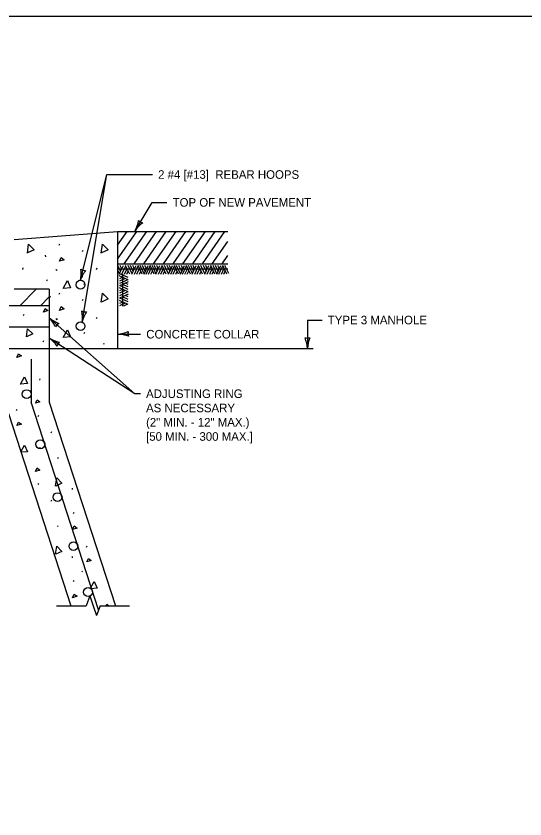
# Model space of a CAD drawing. Extents: x 49991.4 to 50021, y 49987.6 to 50011.4.
# Drawn here: x 50005.05 to 50008.62, y 49993.37 to 49999 of the extents above; entities that cross this region are included whole.
import ezdxf

# ---------------------------------------------------------------- set-up
doc = ezdxf.new("R2010")
doc.units = 0
for name, color, linetype in [('Level 1', 7, 'Continuous'), ('Level 2', 7, 'Continuous'), ('Level 3', 7, 'Continuous'), ('Level 4', 7, 'Continuous'), ('Level 6', 7, 'Continuous')]:
    doc.layers.add(name, color=color, linetype=linetype)

msp = doc.modelspace()

# ---------------------------------------------------------------- linework, layer by layer
at = {"layer": 'Level 1'}
for p, q in [((50005.0384, 49997.4313), (50005.7649, 49997.4869)), ((50005.7649, 49997.2938), (50005.9001, 49997.4869)), ((50005.7649, 49997.4869), (50006.5384, 49997.4869)), ((50005.7649, 49997.4869), (50005.7649, 49996.6669)), ((50005.7651, 49997.3923), (50005.8314, 49997.4869)), ((50005.8113, 49997.2619), (50005.9688, 49997.4869)), ((50005.8799, 49997.2619), (50006.0374, 49997.4869)), ((50005.9486, 49997.2619), (50006.1062, 49997.4869)), ((50006.0173, 49997.2619), (50006.1748, 49997.4869)), ((50006.0859, 49997.2619), (50006.2435, 49997.4869)), ((50006.1546, 49997.2619), (50006.3121, 49997.4869)), ((50006.2232, 49997.2619), (50006.3808, 49997.4869)), ((50006.2919, 49997.2619), (50006.4495, 49997.4869)), ((50006.3606, 49997.2619), (50006.5181, 49997.4869)), ((50005.3541, 49997.3925), (50005.3585, 49997.4022)), ((50006.4292, 49997.2619), (50006.5384, 49997.4178)), ((50005.2575, 49997.3209), (50005.2586, 49997.3112)), ((50005.5187, 49997.3481), (50005.523, 49997.3579)), ((50006.498, 49997.2619), (50006.5384, 49997.3197)), ((50005.7649, 49997.2619), (50006.5384, 49997.2619)), ((50005.0986, 49997.2225), (50005.1029, 49997.2323)), ((50005.3314, 49997.2225), (50005.3357, 49997.216)), ((50005.3357, 49997.2201), (50005.3401, 49997.2136)), ((50005.6172, 49997.2225), (50005.6216, 49997.2323)), ((50005.7649, 49997.2254), (50006.5384, 49997.2254)), ((50005.7784, 49997.1924), (50005.7649, 49997.2213)), ((50005.786, 49997.2088), (50005.7668, 49997.2499)), ((50005.7767, 49997.1886), (50005.8051, 49997.2499)), ((50005.7942, 49997.2265), (50005.7836, 49997.2499)), ((50005.795, 49997.1886), (50005.8222, 49997.2471)), ((50005.8125, 49997.1886), (50005.831, 49997.2284)), ((50005.8495, 49997.1886), (50005.8209, 49997.2499)), ((50005.8299, 49997.1886), (50005.8396, 49997.2097)), ((50005.8662, 49997.1903), (50005.8386, 49997.2499)), ((50005.875, 49997.2093), (50005.8563, 49997.2499)), ((50005.8655, 49997.1886), (50005.8939, 49997.2499)), ((50005.883, 49997.2272), (50005.8727, 49997.2499)), ((50005.8824, 49997.1886), (50005.9095, 49997.2469)), ((50005.9, 49997.1886), (50005.9183, 49997.2284)), ((50005.9369, 49997.1886), (50005.9082, 49997.2499)), ((50005.9179, 49997.1886), (50005.9272, 49997.2091)), ((50005.9508, 49997.1905), (50005.9232, 49997.2499)), ((50005.959, 49997.2082), (50005.9398, 49997.2499)), ((50005.9499, 49997.1886), (50005.9783, 49997.2501)), ((50005.9676, 49997.2267), (50005.9569, 49997.2499)), ((50005.9651, 49997.1886), (50005.9925, 49997.248)), ((50005.9819, 49997.1886), (50006.0009, 49997.2303)), ((50006.0204, 49997.1886), (50005.992, 49997.2499)), ((50005.9981, 49997.1886), (50006.0091, 49997.2128)), ((50006.0204, 49997.2213), (50006.0072, 49997.2499)), ((50006.0339, 49997.1924), (50006.0204, 49997.2213)), ((50006.0415, 49997.2088), (50006.0223, 49997.2499)), ((50006.0322, 49997.1886), (50006.0606, 49997.2499)), ((50006.0497, 49997.2265), (50006.039, 49997.2499)), ((50006.0505, 49997.1886), (50006.0777, 49997.2471)), ((50006.068, 49997.1886), (50006.0865, 49997.2284)), ((50006.1049, 49997.1886), (50006.0764, 49997.2499)), ((50006.0853, 49997.1886), (50006.095, 49997.2097)), ((50006.1217, 49997.1903), (50006.0941, 49997.2499)), ((50006.1305, 49997.2093), (50006.1118, 49997.2499)), ((50006.1209, 49997.1886), (50006.1493, 49997.2499)), ((50006.1385, 49997.2272), (50006.1282, 49997.2499)), ((50006.1379, 49997.1886), (50006.165, 49997.2469)), ((50006.1554, 49997.1886), (50006.1737, 49997.2284)), ((50006.1924, 49997.1886), (50006.1636, 49997.2499)), ((50006.1733, 49997.1886), (50006.1827, 49997.2091)), ((50006.2063, 49997.1905), (50006.1787, 49997.2499)), ((50006.2145, 49997.2082), (50006.1952, 49997.2499)), ((50006.2053, 49997.1886), (50006.2337, 49997.2501)), ((50006.2231, 49997.2267), (50006.2124, 49997.2499)), ((50006.2206, 49997.1886), (50006.248, 49997.248)), ((50006.2373, 49997.1886), (50006.2564, 49997.2303)), ((50006.2758, 49997.1886), (50006.2474, 49997.2499)), ((50006.2535, 49997.1886), (50006.2646, 49997.2128)), ((50006.2758, 49997.2213), (50006.2627, 49997.2499)), ((50006.2893, 49997.1924), (50006.2758, 49997.2213)), ((50006.297, 49997.2088), (50006.2777, 49997.2499)), ((50006.2876, 49997.1886), (50006.316, 49997.2499)), ((50006.3052, 49997.2265), (50006.2945, 49997.2499)), ((50006.3059, 49997.1886), (50006.3332, 49997.2471)), ((50006.3234, 49997.1886), (50006.3419, 49997.2284)), ((50006.3604, 49997.1886), (50006.3318, 49997.2499)), ((50006.3408, 49997.1886), (50006.3505, 49997.2097)), ((50006.3772, 49997.1903), (50006.3495, 49997.2499)), ((50006.3859, 49997.2093), (50006.3673, 49997.2499)), ((50006.3764, 49997.1886), (50006.4048, 49997.2499)), ((50006.3939, 49997.2272), (50006.3836, 49997.2499)), ((50006.3934, 49997.1886), (50006.4204, 49997.2469)), ((50006.4109, 49997.1886), (50006.4292, 49997.2284)), ((50006.4478, 49997.1886), (50006.4191, 49997.2499)), ((50006.4288, 49997.1886), (50006.4381, 49997.2091)), ((50006.4617, 49997.1905), (50006.4341, 49997.2499)), ((50006.4699, 49997.2082), (50006.4507, 49997.2499)), ((50006.4608, 49997.1886), (50006.4892, 49997.2501)), ((50006.4785, 49997.2267), (50006.4678, 49997.2499)), ((50006.476, 49997.1886), (50006.5035, 49997.248)), ((50006.4928, 49997.1886), (50006.5118, 49997.2303)), ((50006.5313, 49997.1886), (50006.5029, 49997.2499)), ((50006.509, 49997.1886), (50006.52, 49997.2128)), ((50006.5313, 49997.2213), (50006.5181, 49997.2499)), ((50006.5448, 49997.1924), (50006.5313, 49997.2213)), ((50005.2675, 49997.1423), (50005.2718, 49997.152)), ((50005.8382, 49997.149), (50005.7767, 49997.1774)), ((50005.8001, 49997.1668), (50005.7769, 49997.1561)), ((50005.8186, 49997.1582), (50005.7769, 49997.139)), ((50005.8363, 49997.15), (50005.7769, 49997.1224)), ((50005.8382, 49997.1643), (50005.7788, 49997.1917)), ((50005.8014, 49996.9641), (50005.8014, 49997.1891)), ((50005.5295, 49997.1174), (50005.5339, 49997.1271)), ((50005.8382, 49997.1361), (50005.7769, 49997.1073)), ((50005.8382, 49997.0647), (50005.7769, 49997.093)), ((50005.8382, 49997.0816), (50005.7799, 49997.1087)), ((50005.8382, 49997.0991), (50005.7984, 49997.1174)), ((50005.8382, 49997.117), (50005.8177, 49997.1264)), ((50005.285, 49997.0845), (50005.0384, 49997.0845)), ((50005.1926, 49997.0845), (50005.0792, 49996.9669)), ((50005.285, 49997.0845), (50005.285, 49996.2919)), ((50005.3541, 49997.0483), (50005.3585, 49997.0581)), ((50005.6649, 49997.0481), (50005.6692, 49997.0416)), ((50005.7996, 49997.0822), (50005.7769, 49997.0719)), ((50005.8175, 49997.0742), (50005.7769, 49997.0555)), ((50005.8365, 49997.0654), (50005.7769, 49997.0378)), ((50005.8382, 49997.0487), (50005.7769, 49997.0201)), ((50005.8382, 49997.029), (50005.8171, 49997.0387)), ((50005.285, 49997.0302), (50005.2238, 49996.9669)), ((50005.5187, 49997.0039), (50005.523, 49997.0137)), ((50005.8382, 49996.9759), (50005.7769, 49997.0043)), ((50005.8003, 49996.9934), (50005.7769, 49996.9827)), ((50005.818, 49996.9852), (50005.7769, 49996.966)), ((50005.8382, 49996.9942), (50005.7797, 49997.0214)), ((50005.8382, 49997.0117), (50005.7984, 49997.0302)), ((50005.8344, 49996.9776), (50005.8055, 49996.9641)), ((50005.285, 49996.9669), (50004.9724, 49996.9669)), ((50005.1048, 49996.8988), (50005.1087, 49996.9078)), ((50005.3314, 49996.8783), (50005.3357, 49996.8718)), ((50005.3357, 49996.8759), (50005.3401, 49996.8694)), ((50005.6172, 49996.8783), (50005.6216, 49996.8881)), ((50005.285, 49996.8169), (50003.1598, 49996.8169)), ((50005.5295, 49996.7732), (50005.5339, 49996.7829)), ((50005.2425, 49996.714), (50005.2467, 49996.723)), ((50005.6649, 49996.7039), (50005.6692, 49996.6974)), ((50002.6613, 49996.6669), (50005.7649, 49996.6669)), ((50005.1578, 49996.5919), (50005.1578, 49996.2919)), ((50005.2181, 49996.4446), (50005.222, 49996.4536)), ((50004.9724, 49996.2919), (50005.4368, 49994.863)), ((50005.6315, 49994.8343), (50005.1578, 49996.2919)), ((50005.285, 49996.2919), (50005.7491, 49994.863)), ((50005.0564, 49996.2316), (50005.0603, 49996.2406)), ((50005.2082, 49996.1908), (50005.2121, 49996.1998)), ((50005.2991, 49996.075), (50005.303, 49996.084)), ((50005.2181, 49995.9661), (50005.222, 49995.9751)), ((50005.3429, 49995.9022), (50005.3471, 49995.8962)), ((50005.2082, 49995.7123), (50005.2121, 49995.7213)), ((50005.4458, 49995.6874), (50005.4467, 49995.6784)), ((50005.2991, 49995.5965), (50005.303, 49995.6055)), ((50005.5139, 49995.5848), (50005.5154, 49995.5827)), ((50005.4548, 49995.5107), (50005.459, 49995.5197)), ((50005.3429, 49995.4237), (50005.3471, 49995.4177)), ((50005.546, 49995.2749), (50005.5502, 49995.2839)), ((50005.4458, 49995.2089), (50005.4467, 49995.1999)), ((50005.5139, 49995.1063), (50005.5178, 49995.1003)), ((50005.4548, 49995.0322), (50005.459, 49995.0412))]:
    msp.add_line(p, q, dxfattribs=at)
msp.add_lwpolyline([(49999.3835, 49998.9992), (50016.7501, 49998.9992), (50016.7501, 49987.7988), (49999.3835, 49987.7988)], close=True, dxfattribs=at)
for points in [[(50005.1318, 49997.3369), (50005.1404, 49997.3988), (50005.1792, 49997.3587), (50005.1328, 49997.3373)], [(50005.6504, 49997.3369), (50005.659, 49997.3988), (50005.6978, 49997.3587), (50005.6514, 49997.3373)], [(50005.3563, 49997.2788), (50005.3693, 49997.3059), (50005.3909, 49997.2896), (50005.3563, 49997.2788)], [(50005.3834, 49997.0881), (50005.4126, 49997.1433), (50005.4353, 49997.0925), (50005.3845, 49997.0881)], [(50005.285, 49997.0379), (50005.2946, 49997.0308), (50005.285, 49997.0278)], [(50005.6504, 49996.9927), (50005.659, 49997.0546), (50005.6978, 49997.0146), (50005.6514, 49996.9931)], [(50005.2438, 49996.923), (50005.2558, 49996.9479), (50005.2759, 49996.9329), (50005.2438, 49996.923)], [(50005.3563, 49996.9346), (50005.3693, 49996.9617), (50005.3909, 49996.9455), (50005.3563, 49996.9346)], [(50005.1256, 49996.749), (50005.1334, 49996.806), (50005.1691, 49996.7691), (50005.1265, 49996.749)], [(50005.3834, 49996.744), (50005.4126, 49996.7992), (50005.4353, 49996.7483), (50005.3845, 49996.744)], [(50005.0582, 49996.6051), (50005.0702, 49996.63), (50005.0903, 49996.615), (50005.0582, 49996.6051)], [(50005.0834, 49996.4176), (50005.1104, 49996.4686), (50005.1314, 49996.4215), (50005.0843, 49996.4176)], [(50005.1884, 49996.2832), (50005.2004, 49996.3081), (50005.2202, 49996.2931), (50005.1884, 49996.2832)], [(50005.0582, 49996.1266), (50005.0702, 49996.1518), (50005.0903, 49996.1368), (50005.0582, 49996.1266)], [(50005.0855, 49995.9436), (50005.1104, 49995.9901), (50005.1314, 49995.943), (50005.087, 49995.9394)], [(50005.1884, 49995.8047), (50005.2004, 49995.8296), (50005.2202, 49995.8146), (50005.1884, 49995.8047)], [(50005.3297, 49995.7021), (50005.3375, 49995.7591), (50005.3732, 49995.7222), (50005.3306, 49995.7024)], [(50005.4479, 49995.3979), (50005.4599, 49995.4228), (50005.48, 49995.4078), (50005.4479, 49995.3979)], [(50005.3297, 49995.2236), (50005.3375, 49995.2806), (50005.3732, 49995.2437), (50005.3306, 49995.2239)], [(50005.3297, 49995.2236), (50005.3375, 49995.2806), (50005.3732, 49995.2437), (50005.3306, 49995.2239)], [(50005.5481, 49995.1702), (50005.5601, 49995.1951), (50005.5802, 49995.1801), (50005.5481, 49995.1702)], [(50005.573, 49994.9824), (50005.6, 49995.0334), (50005.621, 49994.9863), (50005.5742, 49994.9824)], [(50005.4479, 49994.9194), (50005.4599, 49994.9446), (50005.48, 49994.9296), (50005.4479, 49994.9194)], [(50005.6852, 49994.863), (50005.69, 49994.8732), (50005.7038, 49994.863)]]:
    msp.add_lwpolyline(points, dxfattribs=at)
for centre in [(50005.5045, 49997.1147), (50005.5045, 49996.824), (50005.1265, 49996.3472), (50005.2228, 49995.9958), (50005.3433, 49995.6248), (50005.4551, 49995.2808), (50005.5575, 49994.9587)]:
    msp.add_circle(centre, 0.0313, dxfattribs=at)
at = {"layer": 'Level 3'}
for p, q in [((50005.5045, 49997.146), (50005.6899, 49997.8877)), ((50005.5165, 49996.8532), (50005.6898, 49997.8877)), ((50005.6898, 49997.8877), (50006.0086, 49997.8877)), ((50005.8872, 49997.4919), (50006.008, 49997.6919)), ((50006.008, 49997.6919), (50006.1107, 49997.6919)), ((50005.285, 49996.8832), (50005.8844, 49996.3502)), ((50007.0965, 49996.8669), (50007.1992, 49996.8669)), ((50007.0965, 49996.8669), (50007.0965, 49996.6669)), ((50005.7649, 49996.7678), (50005.9257, 49996.7676)), ((50005.823, 49996.7676), (50005.9257, 49996.7676)), ((50005.8844, 49996.3502), (50005.285, 49996.7395)), ((50005.9244, 49996.3502), (50005.8844, 49996.3502))]:
    msp.add_line(p, q, dxfattribs=at)
for centre, radius, start, end in [((50005.6821, 49997.6024), 0.233, 331.6942, 350.9441), ((50006.0726, 49997.3692), 0.2223, 126.3229, 146.5064), ((50005.9535, 49997.6017), 0.0548, 221.0057, 256.7281), ((50005.2765, 49997.1938), 0.233, 348.1508, 7.4006), ((50005.7171, 49997.0808), 0.2223, 142.7795, 162.963), ((50005.537, 49997.27), 0.0548, 237.4623, 273.1847), ((50005.538, 49996.9794), 0.0548, 242.4505, 278.1729), ((50005.2851, 49996.8808), 0.233, 353.139, 12.3889), ((50005.7339, 49996.8066), 0.2223, 147.7677, 167.9512), ((50005.126, 49996.7278), 0.2223, 24.1666, 44.3501), ((50005.4362, 49997.0605), 0.233, 229.5379, 248.7877), ((50005.3783, 49996.7953), 0.0548, 118.8494, 154.5718), ((50005.747, 49997.0001), 0.233, 274.2436, 293.4935), ((50005.7605, 49996.5454), 0.2223, 68.8723, 89.0558), ((50005.8924, 49996.7709), 0.0548, 163.5551, 199.2775), ((50005.1574, 49996.5575), 0.2223, 34.7899, 54.9734), ((50005.4009, 49996.9416), 0.233, 240.1612, 259.411), ((50005.3929, 49996.6703), 0.0548, 129.4727, 165.195), ((50007.0965, 49996.7952), 0.0548, 252.1388, 287.8612), ((50006.8638, 49996.6554), 0.233, 2.8273, 22.0772), ((50007.3187, 49996.6578), 0.2223, 157.456, 177.6395)]:
    msp.add_arc(centre, radius, start, end, dxfattribs=at)
at = {"layer": 'Level 4'}
msp.add_line((50005.7649, 49996.6669), (50007.1365, 49996.6669), dxfattribs=at)
at = {"layer": 'Level 6'}
for p, q in [((50005.5688, 49994.9316), (50005.5445, 49994.863)), ((50005.5688, 49994.9316), (50005.5931, 49994.863)), ((50005.3368, 49994.863), (50005.5445, 49994.863)), ((50005.5931, 49994.863), (50005.6174, 49994.7944)), ((50005.6417, 49994.863), (50005.6174, 49994.7944)), ((50005.6414, 49994.863), (50005.8491, 49994.863))]:
    msp.add_line(p, q, dxfattribs=at)

# ---------------------------------------------------------------- texts
at = {"layer": 'Level 2'}
for s, p in [('2 #4 [#13]  REBAR HOOPS', (50006.0486, 49997.8577)), ('TOP OF NEW PAVEMENT', (50006.1507, 49997.6619)), ('TYPE 3 MANHOLE', (50007.2392, 49996.8369)), ('CONCRETE COLLAR', (50005.9657, 49996.7376)), ('ADJUSTING RING ', (50005.9644, 49996.3202)), ('AS NECESSARY', (50005.9644, 49996.2202)), ('(2" MIN. - 12" MAX.)', (50005.9644, 49996.1202)), ('[50 MIN. - 300 MAX.]', (50005.9644, 49996.0202))]:
    msp.add_text(s, height=0.06, dxfattribs=at).set_placement(p)

doc.saveas('drawing.dxf')
